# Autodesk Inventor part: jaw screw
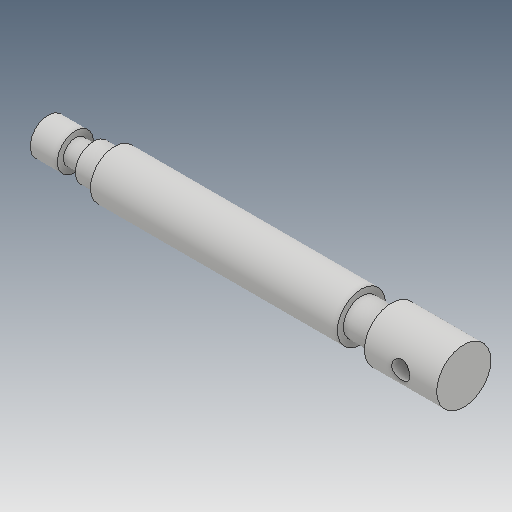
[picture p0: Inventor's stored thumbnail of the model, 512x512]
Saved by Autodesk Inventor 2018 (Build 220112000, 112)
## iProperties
Created: 2016-03
Part Number: jaw screw
Material: Generic
Document SubType Name: Modeling
Designer: Sandeep
Density: 1 g/cm^3
Appearance: Default
Author: Sandeep
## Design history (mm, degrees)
sketch "Sketch1"
  geometry: L1 (0, -138)-(-6, -138); L2 (-6, -116)-(-6, -116); L3 (-6, -116)-(-8, -116); L4 (-8, -116)-(-8, -34); L5 (-8, -34)-(-6, -34); L6 (-6, -34)-(-6, -24); L7 (-6, -24)-(-9, -24); L8 (-9, -24)-(-9, 0); L9 (-9, 0)-(0, 0); L10 (0, 0)-(0, -138); L11 (0, 0)-(0, 14.581); L12 (-6, -116)-(-6, -123); L13 (-6, -123)-(-4, -123); L14 (-4, -123)-(-4, -129); L15 (-4, -129)-(-6, -129); L16 (-6, -129)-(-6, -138); 1 other entity
  constraints: 32 end point, 10 perpendicular, 3 point on line, 3 vertical, 1 coincident, 1 horizontal, 2 other
  dimensions: "d0" = 18 diameter of L8 L11; "d1" = 12 diameter of L6 L11; "d3" = 24 distance of L7.end L8.end; "d4" = 10 distance of L5.end L6.end; "d5" = 82 distance of L3.end L4.end; "d6" = 138 distance between parallel lines of L1 L9; "d8" = 16 diameter of L4 L11; "d10" = 6 distance of L13.end L14.end; "d11" = 9 distance of L15.end L1.end; "d12" = 8 diameter of L14 L11
revolve "Revolution1" sketch "Sketch1" stored, may be unused: angle "d9" = 90 deg
sketch "Sketch2"
  geometry: L1 (0, -9)-(0, 9) reference; L2 (0, 0)-(-20.975, 0); C1 r 3 at (-12, 0)
  constraints: 2 end point, 1 centre point, 1 horizontal, 1 point on line
  dimensions: "d13" = 6 diameter of C1; "d14" = 12 distance from line of L1 C1.centre
extrude "Extrusion1" cut sketch "Sketch2" distance "d15" = 25; taper "d16" = 0 deg
body "Solid1"
